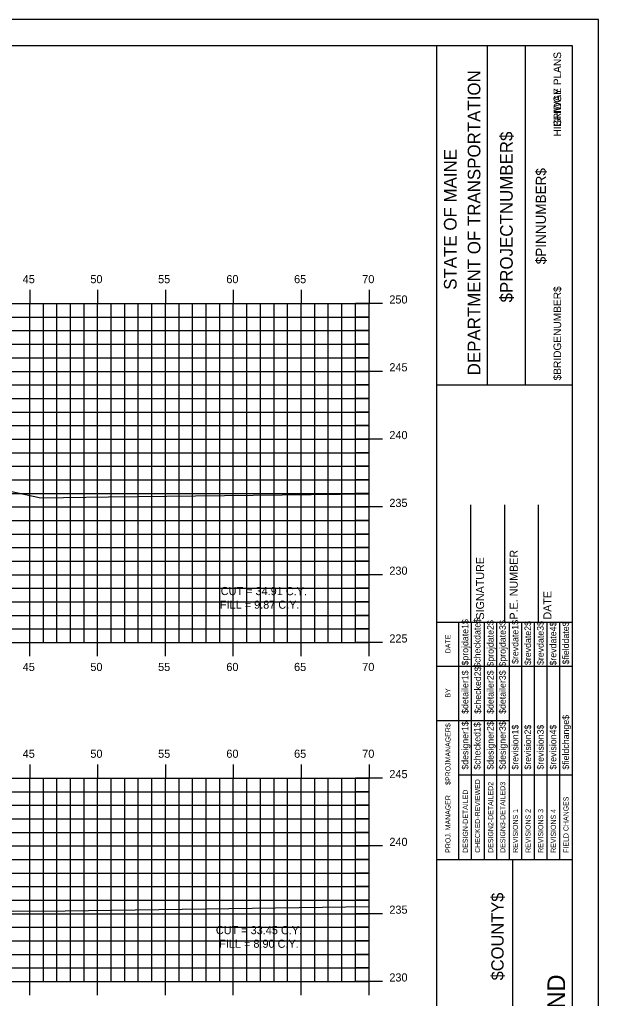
# Model space of a CAD drawing. Extents: x 1160718 to 1173142, y 616002 to 617630.
# Drawn here: x 1167345.6 to 1167388.2, y 616651.7 to 616723.9 of the extents above; entities that cross this region are included whole.
import ezdxf

# ---------------------------------------------------------------- set-up
doc = ezdxf.new("R2010")
doc.units = 0
for name, color, linetype in [('ANNOTATION', 7, 'Continuous'), ('BORDER', 7, 'Continuous'), ('BRIDGE_TITLE', 7, 'Continuous'), ('H_V ANNOTATION', 7, 'Continuous'), ('HIGHWAY_TITLE', 7, 'Continuous'), ('MAJOR', 7, 'Continuous'), ('MINOR', 7, 'Continuous'), ('PLOT BOUNDARY', 7, 'Continuous'), ('S_Roadway_Centerline', 7, 'Continuous')]:
    doc.layers.add(name, color=color, linetype=linetype)

msp = doc.modelspace()

# ---------------------------------------------------------------- linework, layer by layer
at = {"layer": 'BORDER'}
for p, q in [((1167386.316, 616721.928), (1167226.316, 616721.928)), ((1167376.316, 616616.931), (1167376.316, 616721.931)), ((1167380.044, 616696.925), (1167380.044, 616721.925)), ((1167382.839, 616696.925), (1167382.839, 616721.925)), ((1167386.316, 616616.931), (1167386.316, 616721.931)), ((1167376.317, 616696.923), (1167386.316, 616696.923)), ((1167378.816, 616679.431), (1167378.816, 616688.079)), ((1167381.316, 616679.431), (1167381.316, 616688.079)), ((1167383.816, 616679.431), (1167383.816, 616688.079)), ((1167376.316, 616679.431), (1167386.316, 616679.431)), ((1167376.316, 616661.931), (1167386.316, 616661.931)), ((1167381.907, 616626.931), (1167381.907, 616661.931))]:
    msp.add_line(p, q, dxfattribs=at)
for points in [[(1167377.93, 616676.181), (1167377.93, 616679.431)], [(1167378.863, 616661.934), (1167378.863, 616679.431)], [(1167379.795, 616679.431), (1167379.795, 616661.934)], [(1167380.726, 616661.934), (1167380.726, 616679.431)], [(1167381.658, 616661.934), (1167381.658, 616679.431)], [(1167382.59, 616661.934), (1167382.59, 616679.431)], [(1167383.521, 616661.934), (1167383.521, 616679.431)], [(1167384.453, 616661.934), (1167384.453, 616679.431)], [(1167385.385, 616661.934), (1167385.385, 616679.431)], [(1167377.931, 616661.934), (1167377.931, 616678.725)], [(1167376.316, 616676.181), (1167386.316, 616676.181)], [(1167376.316, 616672.181), (1167377.931, 616672.181)], [(1167377.93, 616672.181), (1167381.657, 616672.181)], [(1167377.93, 616668.181), (1167386.316, 616668.181)]]:
    msp.add_lwpolyline(points, dxfattribs=at)
at = {"layer": 'MAJOR'}
for p, q in [((1167346.315, 616703.93), (1167346.315, 616702.928)), ((1167351.315, 616703.93), (1167351.315, 616702.928)), ((1167356.315, 616703.93), (1167356.315, 616702.928)), ((1167361.315, 616703.93), (1167361.315, 616702.928)), ((1167366.315, 616703.93), (1167366.315, 616702.928)), ((1167371.315, 616703.93), (1167371.315, 616702.928)), ((1167231.315, 616702.928), (1167371.315, 616702.928)), ((1167231.315, 616702.928), (1167371.315, 616702.928)), ((1167346.315, 616677.928), (1167346.315, 616702.928)), ((1167351.315, 616677.928), (1167351.315, 616702.928)), ((1167356.315, 616677.928), (1167356.315, 616702.928)), ((1167361.315, 616677.928), (1167361.315, 616702.928)), ((1167366.315, 616677.928), (1167366.315, 616702.928)), ((1167372.317, 616702.928), (1167370.313, 616702.928)), ((1167371.315, 616677.928), (1167371.315, 616702.928)), ((1167371.315, 616677.928), (1167371.315, 616702.928)), ((1167231.315, 616697.928), (1167371.315, 616697.928)), ((1167372.317, 616697.928), (1167370.313, 616697.928)), ((1167231.315, 616692.928), (1167371.315, 616692.928)), ((1167372.317, 616692.928), (1167370.313, 616692.928)), ((1167231.315, 616687.928), (1167371.315, 616687.928)), ((1167372.317, 616687.928), (1167370.313, 616687.928)), ((1167231.315, 616682.928), (1167371.315, 616682.928)), ((1167372.317, 616682.928), (1167370.313, 616682.928)), ((1167231.315, 616677.928), (1167371.315, 616677.928)), ((1167231.315, 616677.928), (1167371.315, 616677.928)), ((1167346.315, 616676.926), (1167346.315, 616677.928)), ((1167351.315, 616676.926), (1167351.315, 616677.928)), ((1167356.315, 616676.926), (1167356.315, 616677.928)), ((1167361.315, 616676.926), (1167361.315, 616677.928)), ((1167366.315, 616676.926), (1167366.315, 616677.928)), ((1167372.317, 616677.928), (1167370.313, 616677.928)), ((1167371.315, 616676.926), (1167371.315, 616677.928)), ((1167346.315, 616668.93), (1167346.315, 616667.928)), ((1167351.315, 616668.93), (1167351.315, 616667.928)), ((1167356.315, 616668.93), (1167356.315, 616667.928)), ((1167361.315, 616668.93), (1167361.315, 616667.928)), ((1167366.315, 616668.93), (1167366.315, 616667.928)), ((1167371.315, 616668.93), (1167371.315, 616667.928)), ((1167231.315, 616667.928), (1167371.315, 616667.928)), ((1167231.315, 616667.928), (1167371.315, 616667.928)), ((1167346.315, 616652.928), (1167346.315, 616667.928)), ((1167351.315, 616652.928), (1167351.315, 616667.928)), ((1167356.315, 616652.928), (1167356.315, 616667.928)), ((1167361.315, 616652.928), (1167361.315, 616667.928)), ((1167366.315, 616652.928), (1167366.315, 616667.928)), ((1167372.317, 616667.928), (1167370.313, 616667.928)), ((1167371.315, 616652.928), (1167371.315, 616667.928)), ((1167371.315, 616652.928), (1167371.315, 616667.928)), ((1167231.315, 616662.928), (1167371.315, 616662.928)), ((1167372.317, 616662.928), (1167370.313, 616662.928)), ((1167231.315, 616657.928), (1167371.315, 616657.928)), ((1167372.317, 616657.928), (1167370.313, 616657.928)), ((1167231.315, 616652.928), (1167371.315, 616652.928)), ((1167231.315, 616652.928), (1167371.315, 616652.928)), ((1167346.315, 616651.926), (1167346.315, 616652.928)), ((1167351.315, 616651.926), (1167351.315, 616652.928)), ((1167356.315, 616651.926), (1167356.315, 616652.928)), ((1167361.315, 616651.926), (1167361.315, 616652.928)), ((1167366.315, 616651.926), (1167366.315, 616652.928)), ((1167372.317, 616652.928), (1167370.313, 616652.928)), ((1167371.315, 616651.926), (1167371.315, 616652.928))]:
    msp.add_line(p, q, dxfattribs=at)
at = {"layer": 'MINOR'}
for p, q in [((1167347.315, 616677.928), (1167347.315, 616702.928)), ((1167348.315, 616677.928), (1167348.315, 616702.928)), ((1167349.315, 616677.928), (1167349.315, 616702.928)), ((1167350.315, 616677.928), (1167350.315, 616702.928)), ((1167352.315, 616677.928), (1167352.315, 616702.928)), ((1167353.315, 616677.928), (1167353.315, 616702.928)), ((1167354.315, 616677.928), (1167354.315, 616702.928)), ((1167355.315, 616677.928), (1167355.315, 616702.928)), ((1167357.315, 616677.928), (1167357.315, 616702.928)), ((1167358.315, 616677.928), (1167358.315, 616702.928)), ((1167359.315, 616677.928), (1167359.315, 616702.928)), ((1167360.315, 616677.928), (1167360.315, 616702.928)), ((1167362.315, 616677.928), (1167362.315, 616702.928)), ((1167363.315, 616677.928), (1167363.315, 616702.928)), ((1167364.315, 616677.928), (1167364.315, 616702.928)), ((1167365.315, 616677.928), (1167365.315, 616702.928)), ((1167367.315, 616677.928), (1167367.315, 616702.928)), ((1167368.315, 616677.928), (1167368.315, 616702.928)), ((1167369.315, 616677.928), (1167369.315, 616702.928)), ((1167370.315, 616677.928), (1167370.315, 616702.928)), ((1167231.315, 616701.928), (1167371.315, 616701.928)), ((1167371.315, 616701.928), (1167370.313, 616701.928)), ((1167231.315, 616700.928), (1167371.315, 616700.928)), ((1167371.315, 616700.928), (1167370.313, 616700.928)), ((1167231.315, 616699.928), (1167371.315, 616699.928)), ((1167371.315, 616699.928), (1167370.313, 616699.928)), ((1167231.315, 616698.928), (1167371.315, 616698.928)), ((1167371.315, 616698.928), (1167370.313, 616698.928)), ((1167231.315, 616696.928), (1167371.315, 616696.928)), ((1167371.315, 616696.928), (1167370.313, 616696.928)), ((1167231.315, 616695.928), (1167371.315, 616695.928)), ((1167371.315, 616695.928), (1167370.313, 616695.928)), ((1167231.315, 616694.928), (1167371.315, 616694.928)), ((1167371.315, 616694.928), (1167370.313, 616694.928)), ((1167231.315, 616693.928), (1167371.315, 616693.928)), ((1167371.315, 616693.928), (1167370.313, 616693.928)), ((1167231.315, 616691.928), (1167371.315, 616691.928)), ((1167371.315, 616691.928), (1167370.313, 616691.928)), ((1167231.315, 616690.928), (1167371.315, 616690.928)), ((1167371.315, 616690.928), (1167370.313, 616690.928)), ((1167231.315, 616689.928), (1167371.315, 616689.928)), ((1167371.315, 616689.928), (1167370.313, 616689.928)), ((1167231.315, 616688.928), (1167371.315, 616688.928)), ((1167371.315, 616688.928), (1167370.313, 616688.928)), ((1167231.315, 616686.928), (1167371.315, 616686.928)), ((1167371.315, 616686.928), (1167370.313, 616686.928)), ((1167231.315, 616685.928), (1167371.315, 616685.928)), ((1167371.315, 616685.928), (1167370.313, 616685.928)), ((1167231.315, 616684.928), (1167371.315, 616684.928)), ((1167371.315, 616684.928), (1167370.313, 616684.928)), ((1167231.315, 616683.928), (1167371.315, 616683.928)), ((1167371.315, 616683.928), (1167370.313, 616683.928)), ((1167231.315, 616681.928), (1167371.315, 616681.928)), ((1167371.315, 616681.928), (1167370.313, 616681.928)), ((1167231.315, 616680.928), (1167371.315, 616680.928)), ((1167371.315, 616680.928), (1167370.313, 616680.928)), ((1167231.315, 616679.928), (1167371.315, 616679.928)), ((1167371.315, 616679.928), (1167370.313, 616679.928)), ((1167231.315, 616678.928), (1167371.315, 616678.928)), ((1167371.315, 616678.928), (1167370.313, 616678.928)), ((1167347.315, 616652.928), (1167347.315, 616667.928)), ((1167348.315, 616652.928), (1167348.315, 616667.928)), ((1167349.315, 616652.928), (1167349.315, 616667.928)), ((1167350.315, 616652.928), (1167350.315, 616667.928)), ((1167352.315, 616652.928), (1167352.315, 616667.928)), ((1167353.315, 616652.928), (1167353.315, 616667.928)), ((1167354.315, 616652.928), (1167354.315, 616667.928)), ((1167355.315, 616652.928), (1167355.315, 616667.928)), ((1167357.315, 616652.928), (1167357.315, 616667.928)), ((1167358.315, 616652.928), (1167358.315, 616667.928)), ((1167359.315, 616652.928), (1167359.315, 616667.928)), ((1167360.315, 616652.928), (1167360.315, 616667.928)), ((1167362.315, 616652.928), (1167362.315, 616667.928)), ((1167363.315, 616652.928), (1167363.315, 616667.928)), ((1167364.315, 616652.928), (1167364.315, 616667.928)), ((1167365.315, 616652.928), (1167365.315, 616667.928)), ((1167367.315, 616652.928), (1167367.315, 616667.928)), ((1167368.315, 616652.928), (1167368.315, 616667.928)), ((1167369.315, 616652.928), (1167369.315, 616667.928)), ((1167370.315, 616652.928), (1167370.315, 616667.928)), ((1167231.315, 616666.928), (1167371.315, 616666.928)), ((1167371.315, 616666.928), (1167370.313, 616666.928)), ((1167231.315, 616665.928), (1167371.315, 616665.928)), ((1167371.315, 616665.928), (1167370.313, 616665.928)), ((1167231.315, 616664.928), (1167371.315, 616664.928)), ((1167371.315, 616664.928), (1167370.313, 616664.928)), ((1167231.315, 616663.928), (1167371.315, 616663.928)), ((1167371.315, 616663.928), (1167370.313, 616663.928)), ((1167231.315, 616661.928), (1167371.315, 616661.928)), ((1167371.315, 616661.928), (1167370.313, 616661.928)), ((1167231.315, 616660.928), (1167371.315, 616660.928)), ((1167371.315, 616660.928), (1167370.313, 616660.928)), ((1167231.315, 616659.928), (1167371.315, 616659.928)), ((1167371.315, 616659.928), (1167370.313, 616659.928)), ((1167231.315, 616658.928), (1167371.315, 616658.928)), ((1167371.315, 616658.928), (1167370.313, 616658.928)), ((1167231.315, 616656.928), (1167371.315, 616656.928)), ((1167371.315, 616656.928), (1167370.313, 616656.928)), ((1167231.315, 616655.928), (1167371.315, 616655.928)), ((1167371.315, 616655.928), (1167370.313, 616655.928)), ((1167231.315, 616654.928), (1167371.315, 616654.928)), ((1167371.315, 616654.928), (1167370.313, 616654.928)), ((1167231.315, 616653.928), (1167371.315, 616653.928)), ((1167371.315, 616653.928), (1167370.313, 616653.928))]:
    msp.add_line(p, q, dxfattribs=at)
at = {"layer": 'PLOT BOUNDARY'}
msp.add_lwpolyline([(1167218.222, 616613.869), (1167388.222, 616613.869), (1167388.222, 616723.869), (1167218.222, 616723.869)], close=True, dxfattribs=at)
at = {"layer": 'S_Roadway_Centerline'}
for points in [[(1167344.861, 616689.092), (1167347.135, 616688.61), (1167352.118, 616688.684), (1167371.315, 616688.896)], [(1167302.528, 616662.541), (1167304.53, 616662.503), (1167307.54, 616662.453), (1167309.222, 616662.422), (1167312.551, 616662.352), (1167313.988, 616662.323), (1167314.59, 616662.311), (1167316.919, 616662.249), (1167317.563, 616662.231), (1167318.608, 616662.19), (1167322.574, 616662.032), (1167323.301, 616661.973), (1167327.586, 616661.631), (1167329.21, 616661.556), (1167329.832, 616661.527), (1167331.421, 616661.09), (1167331.896, 616660.956), (1167332.666, 616660.765), (1167334.118, 616660.446), (1167345.087, 616658.117), (1167348.917, 616658.137), (1167371.315, 616658.466)]]:
    msp.add_lwpolyline(points, dxfattribs=at)

# ---------------------------------------------------------------- texts
at = {"layer": 'ANNOTATION'}
for s, p in [('CUT = 34.91 C.Y.', (1167360.388, 616681.428)), ('FILL = 9.87 C.Y.', (1167360.327, 616680.426)), ('CUT = 33.45 C.Y.', (1167360.029, 616656.423)), ('FILL = 8.90 C.Y.', (1167360.274, 616655.421))]:
    msp.add_text(s, height=0.6, rotation=359.92408, dxfattribs=at).set_placement(p)
at = {"layer": 'BORDER'}
for s, height, p in [('DEPARTMENT OF TRANSPORTATION', 0.93176, (1167379.522, 616697.634)), ('$PROJECTNUMBER$', 0.93176, (1167381.908, 616703.008)), ('STATE OF MAINE', 0.93176, (1167377.771, 616703.94)), ('$PINNUMBER$', 0.74527, (1167384.352, 616705.825)), ('P.E. NUMBER', 0.59055, (1167382.276, 616679.624)), ('SIGNATURE', 0.5906, (1167379.796, 616679.624)), ('DATE', 0.5906, (1167384.757, 616679.624)), ('$projdate1$', 0.48455, (1167378.639, 616676.232)), ('$checkdate$', 0.48455, (1167379.533, 616676.074)), ('$projdate2$', 0.48455, (1167380.502, 616676.153)), ('$projdate3$', 0.48455, (1167381.396, 616676.153)), ('$revdate1$', 0.4845, (1167382.328, 616676.35)), ('$revdate2$', 0.4845, (1167383.26, 616676.271)), ('$revdate3$', 0.4845, (1167384.191, 616676.271)), ('$revdate4$', 0.4845, (1167385.123, 616676.232)), ('$fielddate$', 0.48455, (1167386.055, 616676.31)), ('DATE', 0.3714, (1167377.32, 616677.137)), ('$checked2$', 0.4845, (1167379.57, 616672.667)), ('$detailer1$', 0.48455, (1167378.639, 616672.667)), ('$detailer2$', 0.48455, (1167380.502, 616672.667)), ('$detailer3$', 0.48455, (1167381.396, 616672.667)), ('BY', 0.3714, (1167377.32, 616673.866)), ('$fieldchange$', 0.48455, (1167386.055, 616668.555)), ('$PROJMANAGER$', 0.37275, (1167377.32, 616667.426)), ('$designer1$', 0.48455, (1167378.639, 616668.555)), ('$checked1$', 0.4845, (1167379.533, 616668.555)), ('$designer2$', 0.48455, (1167380.502, 616668.555)), ('$designer3$', 0.48455, (1167381.396, 616668.555)), ('$revision1$', 0.48455, (1167382.328, 616668.555)), ('$revision2$', 0.48455, (1167383.26, 616668.555)), ('$revision3$', 0.48455, (1167384.191, 616668.555)), ('$revision4$', 0.48455, (1167385.123, 616668.555)), ('CHECKED-REVIEWED', 0.37275, (1167379.497, 616662.419)), ('DESIGN2-DETAILED2', 0.37275, (1167380.466, 616662.419)), ('DESIGN3-DETAILED3', 0.37275, (1167381.36, 616662.419)), ('PROJ. MANAGER', 0.37275, (1167377.32, 616662.419)), ('DESIGN-DETAILED', 0.37275, (1167378.602, 616662.419)), ('FIELD CHANGES', 0.37275, (1167386.018, 616662.419)), ('REVISIONS 1', 0.37275, (1167382.292, 616662.419)), ('REVISIONS 2', 0.37275, (1167383.223, 616662.419)), ('REVISIONS 3', 0.37275, (1167384.155, 616662.419)), ('REVISIONS 4', 0.37275, (1167385.087, 616662.419)), ('DIVERSION I-95 NORTHBOUND  ', 1.30428, (1167385.77, 616627.379))]:
    msp.add_text(s, height=height, rotation=90, dxfattribs=at).set_placement(p)
at = {"layer": 'BRIDGE_TITLE'}
for s, height, p in [('BRIDGE PLANS', 0.55901, (1167385.474, 616715.953)), ('$BRIDGENUMBER$', 0.55901, (1167385.474, 616697.259)), ('$COUNTY$', 0.9072, (1167381.236, 616653.011))]:
    msp.add_text(s, height=height, rotation=90, dxfattribs=at).set_placement(p)
at = {"layer": 'H_V ANNOTATION'}
for s, p in [('45', (1167345.794, 616704.428)), ('50', (1167350.78, 616704.428)), ('55', (1167355.772, 616704.428)), ('60', (1167360.802, 616704.428)), ('65', (1167365.794, 616704.428)), ('70', (1167370.818, 616704.428)), ('250', (1167372.815, 616702.928)), ('245', (1167372.815, 616697.928)), ('240', (1167372.815, 616692.928)), ('235', (1167372.815, 616687.928)), ('230', (1167372.815, 616682.928)), ('225', (1167372.815, 616677.928)), ('45', (1167345.794, 616675.828)), ('50', (1167350.78, 616675.828)), ('55', (1167355.772, 616675.828)), ('60', (1167360.802, 616675.828)), ('65', (1167365.794, 616675.828)), ('70', (1167370.818, 616675.828)), ('45', (1167345.794, 616669.428)), ('50', (1167350.78, 616669.428)), ('55', (1167355.772, 616669.428)), ('60', (1167360.802, 616669.428)), ('65', (1167365.794, 616669.428)), ('70', (1167370.818, 616669.428)), ('245', (1167372.815, 616667.928)), ('240', (1167372.815, 616662.928)), ('235', (1167372.815, 616657.928)), ('230', (1167372.815, 616652.928))]:
    msp.add_text(s, height=0.6, dxfattribs=at).set_placement(p)
at = {"layer": 'HIGHWAY_TITLE'}
msp.add_text('HIGHWAY PLANS', height=0.55901, rotation=90, dxfattribs=at).set_placement((1167385.474, 616715.244))

doc.saveas('drawing.dxf')
